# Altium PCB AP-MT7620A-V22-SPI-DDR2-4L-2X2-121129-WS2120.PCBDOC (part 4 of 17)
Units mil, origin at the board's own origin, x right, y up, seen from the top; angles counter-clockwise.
Board outline 7316 x 4279 mil, 4 copper layers (Top, Inner Layer 2, Inner Layer 3, Bottom), stack 35.4 mil thick; 640 components, 473 nets, 2041 pads, 2358 vias.
Unrouted connection lines stored in the file: 11.
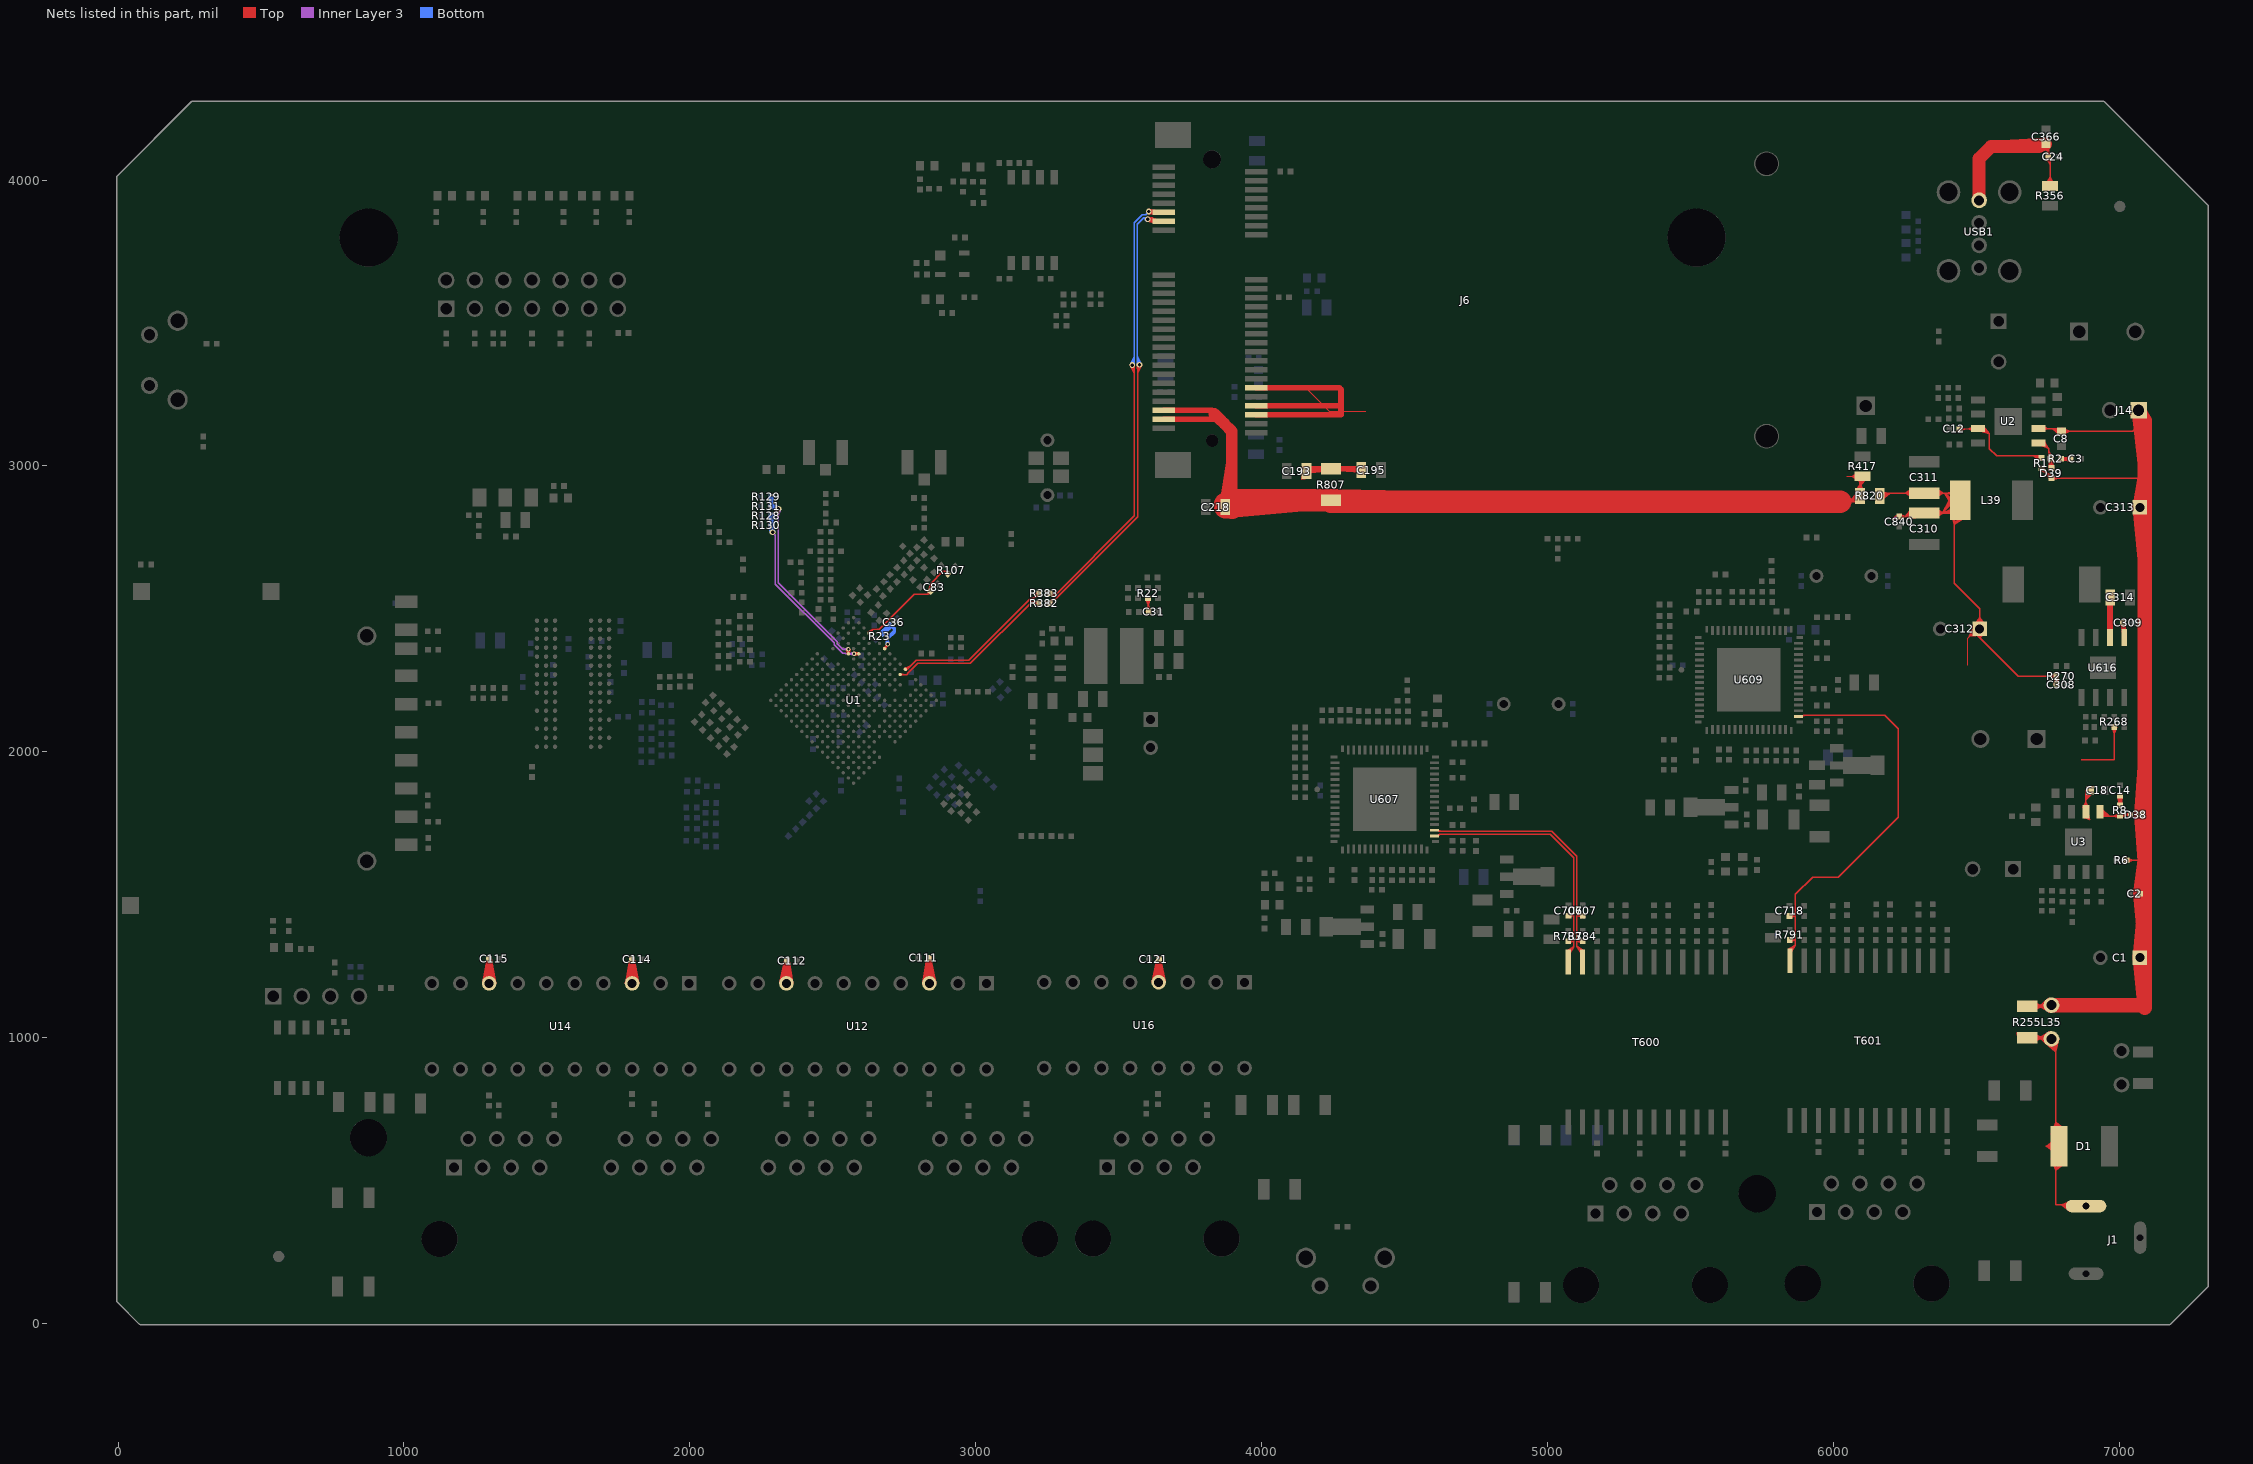
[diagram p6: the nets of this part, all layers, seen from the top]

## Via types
v1: diameter 20, hole 12, Top to Bottom, 2117 vias
v2: diameter 16, hole 8, Top to Bottom, 241 vias

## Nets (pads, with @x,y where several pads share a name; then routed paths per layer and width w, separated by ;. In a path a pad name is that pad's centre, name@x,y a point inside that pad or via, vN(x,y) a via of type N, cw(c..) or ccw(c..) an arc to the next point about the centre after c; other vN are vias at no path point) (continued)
5VA: C308.1 C310.1 C311.1 C312.1 C840.1 L39.2 R270.1 R820.2 | length 7481.4
  Top w4: 6206,2813.5 6219,2826.5 ; C840.1@6227.12,2829.99 6206.44,2813.94 ; C840.1@6229.33,2826.64 6206.44,2813.94 ; C840.1@6232.09,2819.15 6206.44,2813.94 ; C840.1@6232.59,2815.16 6206.44,2813.94 ; 6470.5,2302.5 6470.5,2398 6507.5,2435 C312.1@6511.9,2435 ; C312.1@6493.37,2444.6 6475.96,2403.46 ; C312.1@6497.09,2442.82 6475.96,2403.46 ; C312.1@6500.59,2440.73 6475.96,2403.46 ; C312.1@6503.86,2438.35 6475.96,2403.46 ; C312.1@6506.89,2435.7 6475.96,2403.46 ; C312.1@6515.87,2423.53 6475.96,2403.46 ; C312.1@6517.52,2419.86 6475.96,2403.46 ; C312.1@6518.83,2416.04 6475.96,2403.46 ; C312.1@6519.8,2412.07 6475.96,2403.46 ; C312.1@6520.41,2408 6475.96,2403.46 ; 6206.44,2813.94 C840.1@6231,2823 ; 6219,2826.5 6227.5,2826.5 C840.1@6231,2823 ; 6219,2826.5 6226.42,2816.44 6219,2826.5 ; 6219,2826.5 6230.66,2830.99 6219,2826.5 ; 6219,2826.5 6229.28,2819.39 6219,2826.5 ; 6219,2826.5 6231.49,2826.97 6219,2826.5 ; 6219,2826.5 C840.1@6231,2823 ; 6219,2826.5 C840.1@6231,2823
  Top w4.5: R820.2@6161.07,2905.16 6197.15,2904.88 ; R820.2@6161.32,2900.64 6197.15,2904.88 ; R820.2@6161.39,2909.71 6197.15,2904.88 ; R820.2@6164.46,2889.61 6197.15,2904.88 ; R820.2@6166.63,2885.64 6197.15,2904.88 ; R820.2@6169.3,2881.94 6197.15,2904.88 ; C840.1@6231,2823 6310,2823 6310,2827.12 C310.1@6318,2835.12 6438,2835.12 6438,2880 L39.2@6423,2880 ; C840.1@6231.22,2819.76 6254.5,2823 ; C840.1@6231.22,2826.24 6254.5,2823 ; C840.1@6232.28,2815.36 6254.5,2823 ; C840.1@6232.28,2830.64 6254.5,2823 ; C310.1@6274.76,2849.55 6251.11,2823 ; C310.1@6277.99,2846.27 6251.11,2823 ; C311.1@6279.96,2888.06 6251.35,2904.88 ; C311.1@6279.96,2921.7 6251.35,2904.88 ; C310.1@6280.74,2842.65 6251.11,2823 ; C311.1@6282.01,2892.19 6251.35,2904.88 ; C311.1@6282.01,2917.57 6251.35,2904.88 ; C310.1@6282.99,2838.74 6251.11,2823 ; C311.1@6283.46,2896.51 6251.35,2904.88 ; C311.1@6283.46,2913.25 6251.35,2904.88 ; C311.1@6284.3,2900.95 6251.35,2904.88 ; C311.1@6284.3,2908.81 6251.35,2904.88 ; C310.1@6284.54,2835.12 6251.11,2823 ; C311.1@6284.54,2904.88 6251.35,2904.88 ; C310.1@6285.67,2831.35 6251.11,2823 ; C310.1@6286.28,2817.77 6251.11,2823 ; C310.1@6286.45,2826.9 6251.11,2823 ; C310.1@6286.66,2822.36 6251.11,2823 ; C310.1@6351.46,2835.12 6384.65,2835.12 ; C311.1@6351.46,2904.88 6384.65,2904.88 ; C310.1@6351.7,2831.19 6384.65,2835.12 ; C310.1@6351.7,2839.05 6384.65,2835.12 ; C311.1@6351.7,2900.95 6384.65,2904.88 ; C311.1@6351.7,2908.81 6384.65,2904.88 ; C310.1@6352.54,2826.75 6384.65,2835.12 ; C310.1@6352.54,2843.49 6384.65,2835.12 ; C311.1@6352.54,2896.51 6384.65,2904.88 ; C311.1@6352.54,2913.25 6384.65,2904.88 ; C310.1@6353.99,2822.43 6384.65,2835.12 ; C310.1@6353.99,2847.81 6384.65,2835.12 ; C311.1@6353.99,2892.19 6384.65,2904.88 ; C311.1@6353.99,2917.57 6384.65,2904.88 ; C310.1@6356.04,2818.3 6384.65,2835.12 ; C310.1@6356.04,2851.94 6384.65,2835.12 ; C311.1@6356.04,2888.06 6384.65,2904.88 ; C311.1@6356.04,2921.7 6384.65,2904.88 ; L39.2@6409.66,2849.91 6423,2795.81 ; L39.2@6414.27,2850.84 6423,2795.81 ; L39.2@6418.38,2902.88 6380.26,2835.12 ; L39.2@6418.88,2851.37 6423,2795.81 ; L39.2@6421.33,2854.22 6389.1,2904.88 ; L39.2@6422.31,2900.51 6380.26,2835.12 ; L39.2@6423.47,2851.52 6423,2795.81 ; L39.2@6425.16,2856.87 6389.1,2904.88 ; L39.2@6426.09,2897.93 6380.26,2835.12 ; L39.2@6428.03,2851.3 6423,2795.81 ; L39.2@6428.75,2859.79 6389.1,2904.88 ; L39.2@6429.68,2895.14 6380.26,2835.12 ; L39.2@6432.07,2862.94 6389.1,2904.88 ; L39.2@6433.09,2892.16 6380.26,2835.12 ; L39.2@6435.13,2866.32 6389.1,2904.88 ; L39.2@6448.41,2895.48 6389.1,2904.88 ; L39.2@6448.47,2913.84 6389.1,2904.88 ; L39.2@6448.95,2900 6389.1,2904.88 ; L39.2@6448.99,2909.2 6389.1,2904.88 ; L39.2@6449.15,2904.58 6389.1,2904.88 ; L39.2@6451.66,2865.9 6380.26,2835.12 ; L39.2@6453.33,2861.69 6380.26,2835.12 ; L39.2@6454.76,2857.37 6380.26,2835.12 ; L39.2@6455.94,2852.95 6380.26,2835.12 ; L39.2@6456.86,2848.45 6380.26,2835.12 ; L39.2@6457.72,2839.39 6423,2795.81 ; L39.2@6461.17,2836.4 6423,2795.81 ; L39.2@6464.39,2833.11 6423,2795.81 ; L39.2@6467.35,2829.54 6423,2795.81 ; L39.2@6470.03,2825.69 6423,2795.81 ; C312.1@6489.62,2436.97 6511.9,2469.09 ; C312.1@6490.35,2421.04 6511.9,2399.6 ; C312.1@6493.61,2434.54 6511.9,2469.09 ; C312.1@6493.98,2424.16 6511.9,2399.6 ; C312.1@6497.8,2432.63 6511.9,2469.09 ; C312.1@6497.96,2426.62 6511.9,2399.6 ; C312.1@6502.13,2431.24 6511.9,2469.09 ; C312.1@6502.19,2428.41 6511.9,2399.6 ; C312.1@6506.57,2430.36 6511.9,2469.09 ; C312.1@6506.58,2429.53 6511.9,2399.6 ; C312.1@6511.9,2430 C312.1@6511.9,2435 ; C312.1@6517.22,2429.53 6511.9,2399.6 ; C312.1@6517.23,2430.36 6511.9,2469.09 ; C312.1@6521.61,2428.41 6511.9,2399.6 ; C312.1@6521.66,2431.24 6511.9,2469.09 ; C312.1@6525.83,2426.62 6511.9,2399.6 ; C312.1@6526,2432.63 6511.9,2469.09 ; C312.1@6529.81,2424.16 6511.9,2399.6 ; C312.1@6530.18,2434.54 6511.9,2469.09 ; C312.1@6533.45,2421.04 6511.9,2399.6 ; C312.1@6534.17,2436.97 6511.9,2469.09 ; C308.1@6772.27,2235.5 R270.1@6777.63,2258.5 ; C308.1@6772.28,2234.36 R270.1@6774.18,2258.42 ; R270.1@6772.36,2263.72 C308.1@6780,2241.5 ; C308.1@6772.52,2237.03 R270.1@6782.37,2258.5 ; C308.1@6772.88,2238.05 R270.1@6785.82,2258.42 ; C308.1@6776.75,2234.9 R270.1@6777.63,2258.5 ; R270.1@6776.76,2264.78 C308.1@6780,2241.5 ; C308.1@6776.8,2234.43 R270.1@6774.18,2258.42 ; C308.1@6776.8,2235.55 R270.1@6782.37,2258.5 ; C308.1@6776.91,2235.99 R270.1@6785.82,2258.42 ; R270.1@6778.72,2257.36 6756.5,2265 ; R270.1@6778.72,2272.64 6756.5,2265 ; R270.1@6779.78,2261.76 6756.5,2265 ; R270.1@6779.78,2268.24 6756.5,2265 ; C308.1@6783.09,2235.99 R270.1@6774.18,2258.42 ; C308.1@6783.2,2234.43 R270.1@6785.82,2258.42 ; C308.1@6783.2,2235.55 R270.1@6777.63,2258.5 ; C308.1@6783.25,2234.9 R270.1@6782.37,2258.5 ; R270.1@6783.24,2264.78 C308.1@6780,2241.5 ; C308.1@6787.12,2238.05 R270.1@6774.18,2258.42 ; C308.1@6787.48,2237.03 R270.1@6777.63,2258.5 ; R270.1@6787.64,2263.72 C308.1@6780,2241.5 ; C308.1@6787.72,2234.36 R270.1@6785.82,2258.42 ; C308.1@6787.73,2235.5 R270.1@6782.37,2258.5 ; 6197.15,2904.88 R820.2@6162.45,2895 6172.33,2904.88 C311.1@6318,2904.88 6438,2904.88 6443.75,2899.13 L39.2@6443.75,2880 L39.2@6423,2880 ; L39.2@6423,2880 6423,2590 6511.9,2501.1 C312.1@6511.9,2435 ; 6511.9,2399.6 6646.5,2265 R270.1@6780,2265 ; 6511.9,2399.6 C312.1@6511.9,2435 ; 6756.5,2265 R270.1@6780,2265 ; R270.1@6774.18,2258.42 C308.1@6780,2235 ; R270.1@6777.63,2258.5 C308.1@6780,2235 ; C308.1@6780,2235 R270.1@6780,2265 ; C308.1@6780,2235 R270.1@6780,2258.5 ; C308.1@6780,2235 R270.1@6785.82,2258.42 ; C308.1@6780,2235 R270.1@6782.37,2258.5 ; C308.1@6780,2241.5 R270.1@6780,2265 ; R270.1@6780,2258.5 6772.36,2236.28 R270.1@6780,2258.5 ; R270.1@6780,2258.5 6787.64,2236.28 R270.1@6780,2258.5 ; R270.1@6780,2258.5 6776.76,2235.22 R270.1@6780,2258.5 ; R270.1@6780,2258.5 6783.24,2235.22 R270.1@6780,2258.5
5VD_0: C24.1 C366.1 R356.2 USB1.1 | length 1538.3
  Top w4: R356.2@6758,3979.45 6758.5,3979.45 R356.2@6770.45,3967.5
  Top w4.5: C366.1@6735.01,4135.86 6719.8,4117.3 ; C366.1@6735.15,4121.89 6752,4096.75 ; C366.1@6738.27,4132.62 6719.8,4117.3 ; C366.1@6739.12,4124.13 6752,4096.75 ; C366.1@6740.81,4128.89 6719.8,4117.3 ; C366.1@6742,4126.41 6719.8,4117.3 ; C366.1@6742.9,4123.81 6719.8,4117.3 ; C366.1@6743.33,4125.74 6752,4096.75 ; C366.1@6743.66,4114.78 6719.8,4117.3 ; R356.2@6743.69,3983.02 6758,4009.95 ; C366.1@6743.71,4119.36 6719.8,4117.3 ; C24.1@6744.36,4082.28 6752,4104.5 ; C24.1@6744.77,4078.2 6758,4054.77 ; C366.1@6746,4126.41 6752,4096.75 ; R356.2@6747.9,3981.17 6758,4009.95 ; C366.1@6748.72,4126.83 6752,4096.75 ; C24.1@6748.76,4081.22 6752,4104.5 ; C24.1@6748.88,4080.09 6758,4054.77 ; R356.2@6752.28,3979.99 6758,4009.95 ; C366.1@6753.23,4126.99 6752,4096.75 ; C24.1@6755.21,4081.53 6758,4054.77 ; C24.1@6755.24,4081.22 6752,4104.5 ; C366.1@6757.75,4126.46 6752,4096.75 ; R356.2@6758,3979.45 6758,4075 C24.1@6752,4081 ; C24.1@6759.64,4082.28 6752,4104.5 ; C24.1@6759.73,4081.62 6758,4054.77 ; R356.2@6763.72,3979.99 6758,4009.95 ; R356.2@6768.1,3981.17 6758,4009.95 ; R356.2@6772.31,3983.02 6758,4009.95 ; 6719.8,4117.3 6728.91,4126.41 C366.1@6744,4126.41 6752,4118.41 C24.1@6752,4081 ; C24.1@6752,4081 6758,4054.77
  Top w45: USB1.1@6510,3929 6510,4075.3 6552,4117.3 6719.8,4117.3 6742,4126.41 6590.95,4117.3
5VD_E: C218.1 J6.47 J6.49 R417.1 R807.1 R820.1 | length 5514.4
  Top w4: 6047.5,2964.05 R417.1@6102.5,2964.05 ; R417.1@6087.62,2949.56 6062.5,2964.05 ; R417.1@6087.62,2978.54 6062.5,2964.05 ; R417.1@6089.41,2953.25 6062.5,2964.05 ; R417.1@6089.41,2974.85 6062.5,2964.05 ; R417.1@6090.66,2957.1 6062.5,2964.05 ; R417.1@6090.66,2971 6062.5,2964.05 ; R417.1@6091.34,2961.06 6062.5,2964.05 ; R417.1@6091.34,2967.05 6062.5,2964.05 ; R417.1@6091.5,2964.05 6062.5,2964.05
  Top w4.5: 3852,3163.11 3852.44,3163.56 3853.44,3163.56 ; C218.1@3873.45,2856 3894.7,2856 ; C218.1@3874.23,2850.3 3894.7,2856 ; C218.1@3874.23,2861.7 3894.7,2856 ; C218.1@3875.92,2846.05 3894.7,2856 ; C218.1@3875.92,2865.95 3894.7,2856 ; C218.1@3878.57,2842.17 3894.7,2856 ; C218.1@3878.57,2869.83 3894.7,2856 ; 3896,2854.7 3894.7,2856 ; 6018,2869.45 6023.55,2875 ; 6023,2875 6023.55,2875 ; R820.1@6079.24,2909.57 6093.55,2936.5 ; R820.1@6083.45,2907.72 6093.55,2936.5 ; R820.1@6084.24,2906.44 6057.29,2875 ; R820.1@6087.53,2903.29 6057.29,2875 ; R417.1@6087.77,2964.75 6093.55,2931.1 ; R820.1@6087.83,2906.54 6093.55,2936.5 ; R820.1@6090.43,2899.83 6057.29,2875 ; R417.1@6092.32,2965.22 6093.55,2931.1 ; R820.1@6093.55,2906 6093.55,2936.5 ; R820.1@6095.97,2889.78 6057.29,2875 ; R417.1@6096.84,2965.09 6093.55,2931.1 ; R820.1@6097.35,2885.48 6057.29,2875 ; R820.1@6098.26,2881.02 6057.29,2875 ; R820.1@6099.28,2906.54 6093.55,2936.5 ; R820.1@6103.66,2907.72 6093.55,2936.5 ; R820.1@6107.86,2909.57 6093.55,2936.5 ; R417.1@6107.9,2962.08 6093.55,2931.1 ; R417.1@6111.88,2959.91 6093.55,2931.1 ; R417.1@6115.56,2957.2 6093.55,2931.1 ; 6023.55,2875 6093.55,2875 R820.1@6093.55,2895 ; 6057.29,2875 R820.1@6093.55,2895 ; R820.1@6093.55,2895 6093.55,2955.1 R417.1@6102.5,2964.05 6093.55,2931.1
  Top w20: J6.49@3658,3163.11 3852,3163.11 ; J6.47@3658,3194.61 3826,3194.61 3845,3175.61 3845,3172 ; J6.49@3687.53,3163.11 3757.37,3163.11 ; J6.47@3687.53,3194.61 3757.37,3194.61
  Top w40: 3834.5,3183 3868.75,3148.75 3868.75,3148.25 ; 3845,3172 3853.44,3163.56 3868.75,3148.25 ; 3896,3010.51 C218.1@3873.45,2867 ; 3868.75,3148.25 3896,3121 3896,2879.88 ; C218.1@3873.45,2867 3896,2879.88 ; C218.1@3873.45,2867 3896,2872 3896,2879.88 ; C218.1@3873.45,2867 3896,2879.88
  Top w80: 3967.57,2879.88 R807.1@4227.25,2879.88 ; 4141.88,2879.88 C218.1@3873.45,2856 3896,2854.7 3896,2872 3873.45,2867 3896,2879.88 R807.1@4243,2879.88 4243,2875 6023,2875 ; R807.1@4258.75,2879.88 4518.75,2875
5VD_E_A: C193.1 C195.1 J6.42 J6.46 J6.48 R807.2 | length 2497.6
  Top w4: J6.42@3980.83,3273.35 4034.73,3273.35 4035.58,3272.5 ; J6.42@4010.36,3273.35 4032.2,3273.35 ; J6.42@4010.7,3269.52 4032.2,3273.35 ; J6.42@4010.7,3277.17 4032.2,3273.35 ; J6.42@4011.77,3265.63 4032.2,3273.35 ; J6.42@4011.77,3281.06 4032.2,3273.35 ; C193.1@4143.98,2977.61 4140.5,2953.5 ; C193.1@4148.02,2976.67 4140.5,2953.5 ; C193.1@4151.77,2975.1 4140.5,2953.5 ; C193.1@4155.17,2972.95 4140.5,2953.5 ; 4155.5,3272.5 4236,3192 4364.5,3192 ; C193.1@4157.45,2971 4140.5,2953.5 ; C193.1@4157.45,2982 4157.5,2981.95 4157.5,2970.5 4140.5,2953.5 ; C193.1@4159.47,2968.78 4140.5,2953.5 ; C193.1@4161.73,2965.46 4140.5,2953.5 ; C193.1@4163.42,2961.76 4140.5,2953.5 ; C193.1@4164.49,2957.75 4140.5,2953.5
  Top w20: J6.48@3980.83,3178.86 4278,3178.86 4278,3210.35 ; J6.46@3980.83,3210.35 4278,3210.35 ; J6.42@3980.83,3273.35 4272.15,3273.35 4278,3267.5 4278,3210.35 ; J6.48@4010.36,3178.86 4080.2,3178.86 ; J6.46@4010.36,3210.35 4080.2,3210.35 ; J6.42@4010.36,3273.35 4080.2,3273.35 ; R807.2@4236.58,2990.12 C193.1@4157.45,2982 ; R807.2@4258.75,2990.12 C195.1@4338.43,2990.12 ; R807.2@4270.4,2990.12 C195.1@4348.55,2985 ; R807.2@4270.8,2990.12 C195.1@4348.55,2985 ; C193.1@4157.45,2982 C193.1@4165.57,2990.12 ; C193.1@4157.45,2982 4227.25,2990.12 C193.1@4165.57,2990.12 ; C193.1@4165.57,2990.12 R807.2@4243,2990.12 4343.43,2990.12 C195.1@4348.55,2985
5VEN_5-POWER0: C12.1 R1.2 U2.7 | length 949.2
  Top w4: C12.1@6440.75,3130.25 6441.5,3131 U2.7@6506.39,3131 U2.7@6528,3131 ; C12.1@6441,3130 6463.04,3131 ; C12.1@6441.18,3134 6463.04,3131 ; C12.1@6441.54,3126.04 6463.04,3131 ; C12.1@6442.09,3137.93 6463.04,3131 ; C12.1@6442.81,3122.21 6463.04,3131 ; U2.7@6492.13,3121.02 6470.08,3131 ; U2.7@6492.13,3140.98 6470.08,3131 ; U2.7@6493.49,3124.85 6470.08,3131 ; U2.7@6493.49,3137.15 6470.08,3131 ; U2.7@6494.18,3128.8 6470.08,3131 ; U2.7@6494.18,3133.2 6470.08,3131 ; U2.7@6494.28,3131 6470.08,3131 ; R1.2@6719.91,3035 6721,3035 R1.2@6728,3028
  Top w4.5: C12.1@6440.75,3130.25 C12.1@6441,3130 ; U2.7@6514.43,3121.91 6545.59,3113.41 ; U2.7@6515.92,3126.19 6545.59,3113.41 ; U2.7@6518.5,3131 6545.59,3113.41 ; U2.7@6521.84,3135.31 6545.59,3113.41 ; U2.7@6525.14,3138.41 6545.59,3113.41 ; U2.7@6528,3131 6546,3113 6546,3060 6571,3035 R1.2@6719.91,3035 ; R1.2@6725.17,3020.79 6699.59,3035 ; R1.2@6727.05,3024.89 6699.59,3035 ; R1.2@6728,3028 6699.59,3035 ; R1.2@6728.6,3031.19 6699.59,3035 ; R1.2@6728.84,3035.7 6699.59,3035
12V: C1.1 C2.1 C8.1 C18.1 C313.1 C314.1 D38.1 D39.1 J14.1 L35.2 R1.1 R6.1 R255.2 R268.1 U2.2 U3.2 U616.2 | length 9168.6
  Top w4: C8.1@6795.89,3131 6798,3128.89 C8.1@6798,3120.59 ; U3.2@6877.16,1770.14 6897,1762.5 ; U3.2@6878.98,1773.78 6897,1762.5 ; U3.2@6881.42,1776.97 6897,1762.5 ; U3.2@6883,1778.5 6897,1762.5 ; U3.2@6883,1790.61 6884,1789.61 6884,1775.5 6897,1762.5 ; U3.2@6884.73,1779.87 6897,1762.5 ; U3.2@6888.22,1781.86 6897,1762.5 ; U3.2@6892.07,1783.18 6897,1762.5
  Top w4.5: R255.2@6678,1110.12 6759.06,1110.12 L35.2@6763,1114.06 ; R255.2@6693.75,1110.12 6726.93,1110.12 ; R255.2@6693.98,1106.19 6726.93,1110.12 ; R255.2@6693.98,1114.05 6726.93,1110.12 ; R255.2@6694.82,1101.75 6726.93,1110.12 ; R255.2@6694.82,1118.49 6726.93,1110.12 ; R255.2@6696.27,1097.43 6726.93,1110.12 ; R255.2@6696.27,1122.81 6726.93,1110.12 ; R255.2@6698.33,1093.3 6726.93,1110.12 ; R255.2@6698.33,1126.94 6726.93,1110.12 ; U2.2@6717.61,3131 6748,3131 ; R1.1@6723.51,2985.68 6747.88,2973.12 ; U2.2@6724.5,3131 6748,3131 ; R1.1@6725.91,2989.51 6747.88,2973.12 ; R1.1@6730.37,2994.22 6747.88,2973.12 ; R1.1@6734.08,2996.81 6747.88,2973.12 ; L35.2@6753.03,1137.25 6721.85,1110.12 ; L35.2@6755.9,1133.55 6721.85,1110.12 ; D39.1@6756.68,2952.51 6744.08,2976.92 ; L35.2@6757.61,1089.39 6721.85,1110.12 ; L35.2@6758.3,1129.61 6721.85,1110.12 ; L35.2@6759.73,1093.56 6721.85,1110.12 ; L35.2@6760.23,1125.47 6721.85,1110.12 ; D39.1@6760.52,2954.9 6744.08,2976.92 ; L35.2@6761.34,1097.89 6721.85,1110.12 ; L35.2@6761.68,1121.18 6721.85,1110.12 ; L35.2@6762.45,1102.32 6721.85,1110.12 ; L35.2@6763.05,1106.8 6721.85,1110.12 ; D39.1@6763.22,2953.76 6786.5,2957 ; D39.1@6763.22,2960.24 6786.5,2957 ; D39.1@6764.28,2949.36 6786.5,2957 ; D39.1@6764.28,2964.64 6786.5,2957 ; D39.1@6765.22,2959.37 6744.08,2976.92 ; D39.1@6767.81,2963.08 6744.08,2976.92 ; C8.1@6790.03,3110.47 6766.8,3131 ; C8.1@6792.78,3114.09 6766.8,3131 ; C8.1@6794.96,3118.04 6766.8,3131 ; C8.1@6795.89,3131 6748,3131 ; C8.1@6796,3120.59 6766.8,3131 ; C8.1@6796.81,3123.22 6766.8,3131 ; C8.1@6797.62,3127.66 6766.8,3131 ; C8.1@6797.78,3132.21 6766.8,3131 ; C8.1@6798,3120.59 7048,3120.59 7072.91,3145.5 7089,3145.5 ; C8.1@6800,3120.59 6827.5,3120.59 ; C8.1@6800.14,3117.84 6827.5,3120.59 ; C8.1@6800.14,3123.34 6827.5,3120.59 ; C8.1@6800.96,3113.4 6827.5,3120.59 ; C8.1@6800.96,3127.78 6827.5,3120.59 ; C8.1@6802.51,3109.11 6827.5,3120.59 ; C8.1@6802.51,3132.07 6827.5,3120.59 ; 6866.5,1971.5 6983,1971.5 R268.1@6983,2087 ; U3.2@6883,1790.61 6883,1824.5 ; U3.2@6883,1797.5 6883,1824.5 ; C18.1@6886.09,1866.16 6883,1833.28 ; C18.1@6890.58,1865.43 6883,1833.28 ; C18.1@6894.89,1864.1 6883,1833.28 ; C18.1@6899.83,1861.7 6883,1833.28 ; C18.1@6902,1863.41 6883,1863.41 ; C18.1@6903.55,1859.14 6883,1833.28 ; C18.1@6906.9,1856.07 6883,1833.28 ; R268.1@6975.36,2085.72 6983,2063.5 ; R268.1@6979.76,2086.78 6983,2063.5 ; R268.1@6983,2088 R268.1@6983,2087 ; R268.1@6986.24,2086.78 6983,2063.5 ; R268.1@6990.64,2085.72 6983,2063.5 ; R6.1@7026,1621 7088,1621 7089,1620 ; R6.1@7026.22,1617.76 7049.5,1621 ; R6.1@7026.22,1624.24 7049.5,1621 ; R6.1@7027.28,1613.36 7049.5,1621 ; R6.1@7027.28,1628.64 7049.5,1621 ; D38.1@7071.25,1786.12 7089,1795 ; C313.1@7071.9,2855 C313.1@7089,2855 ; C2.1@7073,1504 7088,1504 ; C2.1@7073.35,1500.77 7088,1504 ; C2.1@7073.35,1507.23 7088,1504 ; D38.1@7073.73,1782.32 7089,1795 ; C2.1@7075,1496.51 7088,1504 ; C2.1@7075,1511.49 7088,1504 ; D38.1@7076.41,1776.78 7089,1780 ; D38.1@7076.41,1783.22 7089,1780 ; D38.1@7078.31,1772.6 7089,1780 ; D38.1@7078.31,1787.4 7089,1780 ; D38.1@7078.62,1778.08 7089,1795 ; D38.1@7082.73,1776.17 7089,1795 ; 7089,1505 7088,1504 ; 7089,2957 D39.1@6763,2957 ; 6744.08,2976.92 D39.1@6763,2957 ; 6747.88,2973.12 R1.1@6728,2992 6728,2993 6758,2963 6758,2962 D39.1@6763,2957 ; 6748,3131 6732.43,3140.58 6748,3131 ; 6748,3131 6732.43,3121.42 6748,3131 ; 6748,3131 6730.53,3136.39 6748,3131 ; 6748,3131 6730.53,3125.61 6748,3131 ; 6748,3131 6729.72,3131 6748,3131 ; 6883,1824.5 6883,1863.41 ; 6883,1824.5 6873.31,1804.99 6883,1824.5 ; 6883,1824.5 6892.69,1804.99 6883,1824.5 ; 6883,1824.5 6877.59,1803.4 6883,1824.5 ; 6883,1824.5 6888.41,1803.4 6883,1824.5 ; 6883,1824.5 6883,1802.72 6883,1824.5 ; 6883,1833.28 C18.1@6897.41,1863 ; 6883,1863.41 6892.32,1852.41 6883,1863.41 ; 6883,1863.41 6892.93,1873.86 6883,1863.41 ; 6883,1863.41 6895.39,1856.04 6883,1863.41 ; 6883,1863.41 6895.79,1870.07 6883,1863.41 ; 6883,1863.41 6897.07,1860.27 6883,1863.41 ; 6883,1863.41 6897.22,1865.74 6883,1863.41 ; 6883,1863.41 C18.1@6897.41,1863 ; 6883,1863.41 C18.1@6897.41,1863 ; 6983,2063.5 R268.1@6983,2087 ; D38.1@7076,1780 7089,1780 ; D38.1@7076,1780 7076,1782 7089,1795 ; D38.1@7076,1780 7089,1795
  Top w20: U616.2@6968,2399.33 6968,2539.45 C314.1@6968.55,2540 ; U616.2@6968,2418.82 6968,2488.86 ; 6968,2452 C314.1@6968.55,2529
  Top w50: L35.2@6763,1114.06 7079.94,1114.06 7089,1105 ; 7089,1335.47 C2.1@7073,1504 ; 7089,1459.74 C1.1@7071.9,1280 7089,1105 ; 7089,1946.31 D38.1@7076,1780 ; 7089,2674.45 C313.1@7071.9,2855 7089,2957 ; J14.1@7068,3195 7063,3190 7063,3185.05 7089,3159.05 ; J14.1@7068,3195 7089,3159.05 ; J14.1@7068,3195 7089,3159.05 ; J14.1@7068,3195 7089,3145.5 ; J14.1@7068,3195 7089,3159.05 ; J14.1@7068,3195 7089,3010.63 J14.1@7068,3195 ; J14.1@7068,3195 7089,3145.5 ; C2.1@7073,1504 7089,1620 ; C2.1@7073,1504 7089,1505 ; C2.1@7073,1504 7089,1505 ; D38.1@7076,1780 7089,1780 ; D38.1@7076,1780 7089,1620 ; D38.1@7076,1780 7089,1795 ; D38.1@7076,1780 7089,1780 ; D38.1@7076,1780 7089,1795 ; 7089,1105 7089,1505 ; 7089,1505 7089,1620 ; 7089,1620 7089,1780 ; 7089,1780 7089,1795 ; 7089,1795 7089,2855 7089,2957 ; 7089,2957 7089,3159.05 ; 7089,2957 7089,3145.5 ; 7089,3145.5 7089,3159.05
12V_L_5-POWER0: D1.2 J1.3 L35.1 R255.1 | length 4520.9
  Top w4: R255.1@6647.35,990.36 6640.5,1017.5 ; R255.1@6651.3,991.68 6640.5,1017.5 ; R255.1@6654.95,993.52 6640.5,1017.5 ; R255.1@6658.24,995.85 6640.5,1017.5 ; R255.1@6662.25,999.88 6640.5,1017.5 ; R255.1@6665.36,1004.64 6640.5,1017.5 ; R255.1@6666.95,1008.35 6640.5,1017.5 ; R255.1@6668,1012.3 6640.5,1017.5 ; R255.1@6668.47,1016.44 6640.5,1017.5 ; R255.1@6678,999.88 6663.88,999.88 6661,997 6640.5,1017.5
  Top w4.5: R255.1@6678,999.88 L35.1@6768.12,999.88 ; R255.1@6693.75,999.88 6726.93,999.88 ; R255.1@6693.98,995.95 6726.93,999.88 ; R255.1@6693.98,1003.81 6726.93,999.88 ; R255.1@6694.82,991.51 6726.93,999.88 ; R255.1@6694.82,1008.25 6726.93,999.88 ; R255.1@6696.27,987.19 6726.93,999.88 ; R255.1@6696.27,1012.57 6726.93,999.88 ; R255.1@6698.33,983.06 6726.93,999.88 ; R255.1@6698.33,1016.7 6726.93,999.88 ; L35.1@6742,981.92 6778,950.74 ; 6742.17,620 6778,620 6778,535 ; L35.1@6745.2,985.28 6778,950.74 ; L35.1@6748.68,988.27 6778,950.74 ; L35.1@6752.39,990.9 6778,950.74 ; L35.1@6753.02,972.75 6721.89,999.88 ; L35.1@6755.9,976.45 6721.89,999.88 ; L35.1@6756.31,993.14 6778,950.74 ; L35.1@6757.61,1020.61 6721.89,999.88 ; L35.1@6758.3,980.39 6721.89,999.88 ; L35.1@6759.73,1016.44 6721.89,999.88 ; L35.1@6760.23,984.53 6721.89,999.88 ; L35.1@6761.34,1012.11 6721.89,999.88 ; L35.1@6761.68,988.82 6721.89,999.88 ; D1.2@6762.18,662.74 6778,704.96 ; L35.1@6762.44,1007.68 6721.89,999.88 ; L35.1@6763,995.94 6772.06,995.94 6776.7,991.3 L35.1@6768.12,999.88 ; L35.1@6763.06,1003.2 6721.89,999.88 ; D1.2@6766.64,661.32 6778,704.96 ; L35.1@6770.04,997.7 6778,950.74 ; D1.2@6771.16,660.39 6778,704.96 ; L35.1@6774.52,998.24 6778,950.74 ; D1.2@6775.71,659.93 6778,704.96 ; L35.1@6779.07,998.36 6778,950.74 ; D1.2@6780.25,659.93 6778,704.96 ; D1.2@6780.77,594.13 6746.39,620 ; D1.2@6780.77,645.87 6746.39,620 ; D1.2@6783.39,598.03 6746.39,620 ; D1.2@6783.39,641.97 6746.39,620 ; L35.1@6783.65,998.03 6778,950.74 ; D1.2@6785.54,602.14 6746.39,620 ; D1.2@6785.54,637.86 6746.39,620 ; D1.2@6787.21,606.4 6746.39,620 ; D1.2@6787.21,633.6 6746.39,620 ; L35.1@6788.22,997.26 6778,950.74 ; D1.2@6788.42,610.78 6746.39,620 ; D1.2@6788.42,629.22 6746.39,620 ; D1.2@6798.1,664.6 6778,704.96 ; D1.2@6802.06,666.82 6778,704.96 ; D1.2@6805.8,669.45 6778,704.96 ; D1.2@6809.28,672.48 6778,704.96 ; D1.2@6812.48,675.9 6778,704.96 ; J1.3@6827.39,393.06 6799.62,415 ; J1.3@6830.02,396.88 6799.62,415 ; J1.3@6831.61,430.14 6799.62,415 ; J1.3@6832.1,400.95 6799.62,415 ; J1.3@6833.32,425.83 6799.62,415 ; J1.3@6833.63,405.21 6799.62,415 ; J1.3@6834.43,421.4 6799.62,415 ; J1.3@6834.79,411 6799.62,415 ; J1.3@6834.96,416.9 6799.62,415 ; J1.3@6884,411 6888,415 6778,415 6778,535 ; L35.1@6768.12,999.88 6778,990 6778,535 ; 6778,535.61 6812.38,563.93 6778,535.61 ; 6778,535.61 6762.18,577.24 6778,535.61 ; 6778,535.61 6809.21,567.39 6778,535.61 ; 6778,535.61 6766.64,578.68 6778,535.61 ; 6778,535.61 6805.75,570.45 6778,535.61 ; 6778,535.61 6771.16,579.62 6778,535.61 ; 6778,535.61 6802.03,573.11 6778,535.61 ; 6778,535.61 6775.71,580.09 6778,535.61 ; 6778,535.61 6798.09,575.36 6778,535.61 ; 6778,535.61 6780.25,580.09 6778,535.61
AA_1-CPU-RT0: C31.2 R22.1 | length 284
  Top w4.5: R22.1@3595.36,2535.72 3603,2513.5 ; C31.2@3597.27,2490.62 3603,2513.65 ; R22.1@3599.76,2536.78 3603,2513.5 ; C31.2@3601.75,2489.95 3603,2513.65 ; R22.1@3606.24,2536.78 3603,2513.5 ; C31.2@3608.21,2490.49 3603,2513.65 ; R22.1@3610.64,2535.72 3603,2513.5 ; C31.2@3612.51,2491.9 3603,2513.65 ; 3603,2513.5 R22.1@3603,2537 3603,2492 C31.2@3605,2490 3603,2513.65
ANT_TRN: R128.2 R130.2 U1.D5 | length 2646.2
  Top w4.5: v2@2574.41,2348.54 U1.D5@2590.69,2346.49 ; v2@2574.45,2337.06 U1.D5@2590.69,2339.22 ; v2@2576.92,2348.1 U1.D5@2590.69,2339.22 ; v2@2576.95,2337.51 U1.D5@2590.69,2346.49 ; v2(2574.7,2342.8) v2@2574.76,2342.86 ; v2(2574.7,2342.8) U1.D5@2591.1,2342.86 ; v2(2574.7,2342.8) U1.D5@2590.69,2339.22 ; v2(2574.7,2342.8) U1.D5@2590.69,2346.49 ; v2(2574.7,2342.8) U1.D5@2591.1,2342.86 ; v2@2574.76,2342.86 U1.D5@2591.1,2342.86 ; v2@2574.76,2342.86 U1.D5@2590.69,2339.22 ; v2@2574.76,2342.86 U1.D5@2590.69,2346.49 ; v2@2574.76,2342.86 U1.D5@2591.1,2342.86 ; U1.D5@2591.1,2342.86 2575.69,2348.46 U1.D5@2591.1,2342.86 ; U1.D5@2591.1,2342.86 2575.73,2337.14 U1.D5@2591.1,2342.86
  Inner Layer 3 w4.5: v1(2289.5,2768.5) 2299.64,2758.36 2299.64,2587 2504.64,2382 2504.64,2375.36 2535.5,2344.5 2544.4,2344.5 2546.1,2342.8 v2(2574.7,2342.8) ; v2@2574,2337.09 2551.2,2342.8 v2@2574,2348.51
  Bottom w4.5: R128.2@2278.27,2825.98 2283.71,2803.05 ; R128.2@2278.26,2826.93 R130.2@2280.78,2802.27 ; R130.2@2278.31,2793.95 R128.2@2285,2816.52 ; R128.2@2278.31,2825.55 R130.2@2285,2802.98 ; R128.2@2278.33,2825.39 R130.2@2285.62,2802.04 ; R128.2@2278.44,2824.77 R130.2@2287.78,2801.3 ; R128.2@2278.71,2823.87 R130.2@2291.15,2800.81 ; v1@2281.75,2768.3 R130.2@2285,2793 ; v1@2281.75,2768.62 R130.2@2286,2793 ; v1@2281.8,2767.6 R130.2@2282.75,2792.91 ; v1@2281.84,2769.66 R130.2@2289.23,2792.61 ; v1@2282.08,2766.25 R130.2@2278.32,2791.98 ; v1@2282.21,2771.12 R130.2@2293.56,2791.29 ; R130.2@2282.75,2793.09 R128.2@2285,2816.52 ; R128.2@2282.75,2826.34 R130.2@2285.62,2802.04 ; R128.2@2282.75,2826.41 R130.2@2285,2802.98 ; R128.2@2282.75,2826.59 2283.71,2803.05 ; R128.2@2282.78,2826.06 R130.2@2287.78,2801.3 ; R128.2@2282.78,2826.98 R130.2@2280.78,2802.27 ; R128.2@2282.86,2825.66 R130.2@2291.15,2800.81 ; v1@2286.27,2768.12 R130.2@2285,2793 ; v1@2286.26,2768.25 R130.2@2286,2793 ; v1@2286.25,2768.68 R130.2@2289.23,2792.61 ; v1@2286.32,2767.84 R130.2@2282.75,2792.91 ; v1@2286.35,2769.29 R130.2@2293.56,2791.29 ; v1@2286.48,2767.29 R130.2@2278.32,2791.98 ; R128.2@2289.13,2825.61 R130.2@2280.78,2802.27 ; R128.2@2289.21,2825.96 2283.71,2803.05 ; R128.2@2289.22,2826.94 R130.2@2291.15,2800.81 ; R130.2@2289.23,2793.36 R128.2@2285,2816.52 ; R128.2@2289.23,2826.14 R130.2@2285,2802.98 ; R128.2@2289.24,2826.23 R130.2@2285.62,2802.04 ; R128.2@2289.25,2826.52 R130.2@2287.78,2801.3 ; v1@2292.34,2770.08 R130.2@2278.32,2791.98 ; v1@2292.57,2769.57 R130.2@2282.75,2792.91 ; v1@2292.65,2769.29 R130.2@2285,2793 ; v1@2292.68,2769.17 R130.2@2286,2793 ; v1@2292.73,2768.16 R130.2@2293.56,2791.29 ; v1@2292.74,2768.76 R130.2@2289.23,2792.61 ; R128.2@2293.23,2823.7 R130.2@2280.78,2802.27 ; R128.2@2293.48,2824.49 2283.71,2803.05 ; R130.2@2293.58,2794.6 R128.2@2285,2816.52 ; R128.2@2293.58,2824.9 R130.2@2285,2802.98 ; R128.2@2293.63,2825.15 R130.2@2285.62,2802.04 ; R128.2@2293.72,2825.85 R130.2@2287.78,2801.3 ; R128.2@2293.74,2826.88 R130.2@2291.15,2800.81 ; v1@2295.92,2772.84 R130.2@2278.32,2791.98 ; v1@2296.57,2771.68 R130.2@2282.75,2792.91 ; v1@2296.81,2771.07 R130.2@2285,2793 ; v1@2296.91,2770.78 R130.2@2286,2793 ; v1@2297.13,2769.83 R130.2@2289.23,2792.61 ; v1@2297.25,2768.44 R130.2@2293.56,2791.29 ; R130.2@2278.32,2791.98 v1@2285,2771 ; R130.2@2278.32,2791.98 v1(2289.5,2768.5) ; R130.2@2280.78,2802.27 R128.2@2286,2826.5 ; R130.2@2282.75,2792.91 v1@2285,2771 ; R130.2@2282.75,2792.91 v1(2289.5,2768.5) ; 2283.71,2803.05 R128.2@2286,2826.5 ; v1@2285,2771 2287,2771 v1(2289.5,2768.5) ; v1@2285,2771 R130.2@2285,2793 ; v1@2285,2771 R130.2@2293.56,2791.29 ; v1@2285,2771 R130.2@2289.23,2792.61 ; v1@2285,2771 R130.2@2286,2793 ; R130.2@2285,2793 R130.2@2286,2793 ; R130.2@2285,2793 2285,2826.5 R128.2@2286,2826.5 ; R130.2@2285,2793 v1(2289.5,2768.5) ; R130.2@2285,2802.98 R128.2@2286,2826.5 ; R128.2@2285,2816.52 R130.2@2286,2793 ; R130.2@2285.62,2802.04 R128.2@2286,2826.5 ; R130.2@2286,2793 v1(2289.5,2768.5) ; R128.2@2286,2826.5 R130.2@2291.15,2800.81 ; R128.2@2286,2826.5 R130.2@2287.78,2801.3 ; R130.2@2289.23,2792.61 v1(2289.5,2768.5) ; v1(2289.5,2768.5) R130.2@2293.56,2791.29
ANT_TRNB: R129.2 R131.2 U1.E4 | length 2807.2
  Top w4.5: v2@2549.26,2359.11 U1.E4@2551.27,2343.28 ; v2@2549.72,2356.53 U1.E4@2558.54,2343.28 ; v2@2560.26,2356.47 U1.E4@2551.27,2343.28 ; v2@2560.75,2359.04 U1.E4@2558.54,2343.28 ; U1.E4@2551.27,2343.28 v2@2554.9,2358.7 ; U1.E4@2551.27,2343.28 v2(2555,2358.8) ; U1.E4@2554.9,2342.86 v2@2554.9,2358.7 ; U1.E4@2554.9,2342.86 v2@2554.9,2358.7 ; U1.E4@2554.9,2342.86 2560.65,2357.73 U1.E4@2554.9,2342.86 ; U1.E4@2554.9,2342.86 2549.34,2357.8 U1.E4@2554.9,2342.86 ; U1.E4@2554.9,2342.86 v2(2555,2358.8) ; U1.E4@2554.9,2342.86 v2(2555,2358.8) ; v2@2554.9,2358.7 v2(2555,2358.8) ; v2@2554.9,2358.7 U1.E4@2558.54,2343.28 ; v2(2555,2358.8) U1.E4@2558.54,2343.28
  Inner Layer 3 w4.5: v1@2302.34,2848.82 2310,2824.5 ; v1@2306.76,2849.79 2310,2824.5 ; v1@2313.24,2849.79 2310,2824.5 ; v1@2317.66,2848.82 2310,2824.5 ; v2@2554.16,2353.11 2535.23,2358.8 ; v2@2554.16,2364.49 2535.23,2358.8 ; v2(2555,2358.8) 2535.23,2358.8 ; 2310,2824.5 v1(2310,2850) 2310,2591 2516.05,2384.95 2516.05,2377.98 2535.23,2358.8
  Bottom w4.5: R129.2@2277.27,2891.99 R131.2@2282.66,2869.06 ; R129.2@2277.26,2892.95 R131.2@2279.74,2868.65 ; R131.2@2277.31,2860.45 R129.2@2284,2883.02 ; R129.2@2277.31,2891.55 R131.2@2284,2868.98 ; R129.2@2277.33,2891.37 R131.2@2284.62,2868.41 ; R129.2@2277.45,2890.74 R131.2@2286.8,2867.72 ; R129.2@2277.73,2889.82 R131.2@2290.18,2867.24 ; R131.2@2281.75,2859.59 R129.2@2284,2883.02 ; R129.2@2281.75,2892.33 R131.2@2284.62,2868.41 ; R129.2@2281.75,2892.41 R131.2@2284,2868.98 ; R129.2@2281.75,2892.6 R131.2@2282.66,2869.06 ; R129.2@2281.78,2892.05 R131.2@2286.8,2867.72 ; R129.2@2281.79,2892.99 R131.2@2279.74,2868.65 ; R129.2@2281.86,2891.65 R131.2@2290.18,2867.24 ; R131.2@2284.31,2856.32 v1@2305,2853.5 ; R129.2@2288.12,2891.59 R131.2@2279.74,2868.65 ; R129.2@2288.2,2891.95 R131.2@2282.66,2869.06 ; R129.2@2288.22,2892.95 R131.2@2290.18,2867.24 ; R131.2@2288.23,2859.86 R129.2@2284,2883.02 ; R129.2@2288.23,2892.14 R131.2@2284,2868.98 ; R129.2@2288.24,2892.23 R131.2@2284.62,2868.41 ; R129.2@2288.25,2892.52 R131.2@2286.8,2867.72 ; R129.2@2292.21,2889.65 R131.2@2279.74,2868.65 ; R129.2@2292.48,2890.47 R131.2@2282.66,2869.06 ; R131.2@2292.58,2861.1 R129.2@2284,2883.02 ; R129.2@2292.58,2890.9 R131.2@2284,2868.98 ; R129.2@2292.63,2891.13 R131.2@2284.62,2868.41 ; R129.2@2292.72,2891.85 R131.2@2286.8,2867.72 ; R129.2@2292.74,2892.9 R131.2@2290.18,2867.24 ; v1@2304.46,2844.58 R131.2@2288.57,2866.38 ; v1@2305.44,2843.73 R131.2@2286.17,2862.53 ; v1@2306.21,2843.24 R131.2@2285.29,2859.41 ; v1@2307.04,2842.84 R131.2@2284.67,2856.27 ; v1@2307.23,2842.76 R131.2@2290,2853.5 ; v1@2307.87,2847.54 R131.2@2288.57,2866.38 ; v1@2308.31,2842.44 R131.2@2284.19,2851.79 ; v1@2308.32,2847.22 R131.2@2286.17,2862.53 ; v1@2308.66,2847.04 R131.2@2285.29,2859.41 ; v1@2309.02,2846.9 R131.2@2284.67,2856.27 ; v1@2309.19,2846.85 R131.2@2290,2853.5 ; v1@2309.37,2857.72 R131.2@2284.19,2851.79 ; v1@2309.57,2846.78 R131.2@2284.19,2851.79 ; v1@2309.85,2857.75 R131.2@2290,2853.5 ; v1@2310.02,2853.25 R131.2@2284.19,2851.79 ; v1@2310.3,2853.24 R131.2@2290,2853.5 ; v1@2310.58,2853.2 R131.2@2284.67,2856.27 ; v1@2310.73,2857.72 R131.2@2284.67,2856.27 ; v1@2310.97,2853.1 R131.2@2285.29,2859.41 ; v1@2311.34,2852.96 R131.2@2286.17,2862.53 ; v1@2311.67,2857.57 R131.2@2285.29,2859.41 ; v1@2311.81,2852.7 R131.2@2288.57,2866.38 ; v1@2312.58,2857.31 R131.2@2286.17,2862.53 ; v1@2313.77,2856.77 R131.2@2288.57,2866.38 ; R131.2@2279.74,2868.65 R129.2@2285,2892.5 ; R131.2@2282.66,2869.06 R129.2@2285,2892.5 ; R131.2@2284,2859.5 R131.2@2290,2853.5 ; R131.2@2284,2859.5 R131.2@2285,2859.5 ; R131.2@2284,2859.5 2284,2892.5 R129.2@2285,2892.5 ; R131.2@2284,2868.98 R129.2@2285,2892.5 ; R129.2@2284,2883.02 R131.2@2285,2859.5 ; R131.2@2284.19,2851.79 v1@2305,2853.5 ; R131.2@2284.19,2851.79 v1(2310,2850) ; R131.2@2284.62,2868.41 R129.2@2285,2892.5 ; R131.2@2284.67,2856.27 v1(2310,2850) ; R131.2@2285,2859.5 v1@2305,2853.5 ; R129.2@2285,2892.5 R131.2@2290.18,2867.24 ; R129.2@2285,2892.5 R131.2@2286.8,2867.72 ; R131.2@2285.29,2859.41 v1(2310,2850) ; R131.2@2286.17,2862.53 v1@2305,2853.5 ; R131.2@2286.17,2862.53 v1(2310,2850) ; R131.2@2288.57,2866.38 v1@2305,2853.5 ; R131.2@2288.57,2866.38 v1(2310,2850) ; R131.2@2290,2853.5 v1@2305,2853.5 ; R131.2@2290,2853.5 v1(2310,2850) ; v1@2305,2853.5 v1(2310,2850)
APCK_RFCKO_N: J6.13 R382.2 | length 2319.8
  Top w5: R382.2@3253.9,2526.28 3270.88,2532.88 ; R382.2@3258,2520 3270.88,2532.88 ; R382.2@3264.28,2515.9 3270.88,2532.88 ; v1@3565.53,3354.68 3566.5,3324.1 ; v1@3580.08,3351.52 3566.5,3324.1 ; v1@3599.19,3856.05 J6.13@3624.45,3849.88 ; v1@3601.1,3855.55 J6.13@3628.47,3856.02 ; v1@3601.42,3870.48 3618,3868 ; v1@3602.96,3870.44 J6.13@3629.69,3863.2 ; v1@3603.07,3855.58 J6.13@3629.69,3863.2 ; v1@3604.89,3869.92 J6.13@3628.47,3856.02 ; v1@3605.78,3856.52 3618,3868 ; v1@3606.68,3868.86 J6.13@3624.45,3849.88 ; J6.13@3630.74,3863.01 v1@3603.47,3868 ; J6.13@3658,3856.02 3655.02,3859 3627,3859 3618,3868 ; 3270.88,2532.88 3277.5,2532.88 3566.5,2821.88 3566.5,3347.5 v1(3573,3354) 3566.5,3324.1 ; v1(3602,3863) 3601,3864 3601,3867 3602,3868 3618,3868 ; v1(3602,3863) 3618,3868 ; v1(3602,3863) J6.13@3624.45,3849.88 ; v1(3602,3863) J6.13@3629.69,3863.2 ; v1(3602,3863) J6.13@3628.47,3856.02 ; v1@3603.47,3868 J6.13@3624.45,3849.88 ; v1@3603.47,3868 J6.13@3628.47,3856.02 ; 3618,3868 3621.98,3852.6 3618,3868 ; 3618,3868 3632.74,3862 3618,3868 ; 3618,3868 J6.13@3628.47,3856.02 ; 3618,3868 J6.13@3628.47,3856.02
  Bottom w5: v1@3565.56,3353.05 3565.5,3383.21 ; v1@3579.98,3356.75 3565.5,3383.21 ; v1@3598.18,3856.55 3587.06,3867.5 ; v1@3602.37,3870.49 3587.06,3867.5 ; 3565.5,3383.21 v1(3573,3354) 3572,3355 3565.5,3355 3565.5,3845.94 3587.06,3867.5 ; 3587.06,3867.5 3599,3867.5 3602,3864.5 v1(3602,3863) 3587.06,3867.5
APCK_RFCKO_P: J6.11 R383.2 | length 2082.2
  Top w5: R383.2@3255.37,2547.98 3274,2545 ; R383.2@3263.16,2560.44 3274,2545 ; v1@3541.03,3350.23 3555.5,3323.94 ; v1@3555.44,3353.95 3555.5,3323.94 ; v1@3603.09,3882.75 J6.11@3626.57,3880.43 ; v1@3604.64,3897.49 J6.11@3628.1,3894.85 ; v1@3605.41,3882.51 J6.11@3628.47,3887.52 ; v1@3606.04,3882.57 3632,3890 v1@3606.04,3897.43 ; v1@3606.96,3897.24 J6.11@3628.47,3887.52 ; v1@3607.69,3883 J6.11@3628.1,3894.85 ; v1@3609.09,3896.28 J6.11@3626.57,3880.43 ; J6.11@3658,3887.52 3658,3890 v1(3605,3890) ; 3274,2545 3555.5,2826.5 3555.5,3353 v1(3548,3353) 3555.5,3323.94 ; 3274,2545 3267,2545 3257,2555 R383.2@3258,2555 3274,2545 ; v1(3605,3890) J6.11@3626.57,3880.43 ; v1(3605,3890) J6.11@3628.1,3894.85 ; v1(3605,3890) J6.11@3628.47,3887.52
  Bottom w5: v1@3540.96,3355.59 3554.5,3381.57 ; v1@3555.47,3352.29 3554.5,3381.57 ; v1(3605,3890) 3605,3889 3594.5,3878.5 3582.5,3878.5 3554.5,3850.5 3554.5,3353 v1(3548,3353) 3554.5,3381.57
APCK_RFCKON_1-CPU-RT0: R382.1 U1.B11 | length 773.2
  Top w5: U1.B11@2735.86,2270.48 2758.64,2270.48 ; U1.B11@2736.11,2267.08 2758.64,2270.48 ; U1.B11@2736.11,2273.87 2758.64,2270.48 ; R382.1@3218.39,2513.43 3203.75,2525.75 ; R382.1@3222.81,2527.46 3203.75,2525.75 ; R382.1@3223,2520 R382.1@3222,2520 ; 2758.64,2270.48 2765.74,2277.57 2766.06,2277.57 2797.54,2309.05 2980.94,2309.05 3197.64,2525.75 3203.75,2525.75 ; 3203.75,2525.75 3209.5,2520 ; 3203.75,2525.75 R382.1@3222,2520 ; 3209.5,2520 R382.1@3222,2520 ; 3209.5,2520 3219.75,2512.85 3209.5,2520 ; 3209.5,2520 3219.75,2527.15 3209.5,2520 ; 3209.5,2520 R382.1@3222,2520 ; 3209.5,2520 R382.1@3222,2520
APCK_RFCKOP_1-CPU-RT0: R383.1 U1.A11 | length 700.5
  Top w5: U1.A11@2752.38,2291.59 2773.67,2300.74 ; U1.A11@2755.95,2285.81 2773.67,2300.74 ; R383.1@3215.98,2559.48 3203.75,2536.75 ; R383.1@3223,2555 R383.1@3222,2555 3203.75,2536.75 ; R383.1@3226.48,2548.98 3203.75,2536.75 ; 2773.67,2300.74 U1.A11@2753.95,2288.57 2761.5,2288.57 2792.98,2320.05 2976.39,2320.05 3193.08,2536.75 3203.75,2536.75
BBPLL_V12A_1-CPU-RT0: C36.1 R23.2 U1.A7 | length 317.1
  Top w8: U1.A7@2680.6,2361.92 U1.A7@2681.57,2360.95 ; U1.A7@2680.6,2361.92 v2@2693.34,2374.66 ; U1.A7@2680.6,2361.92 v2(2692,2376) ; U1.A7@2681.57,2360.95 v2@2693.34,2374.66 ; U1.A7@2681.57,2360.95 v2(2692,2376) ; v2(2692,2376) v2@2693.34,2374.66
  Bottom w12: C36.1@2700.27,2441.27 2704.56,2441.27 2716,2429.83 2716,2421 2690,2395 ; 2690,2395 2690,2376 v2(2692,2376) 2690,2395
  Bottom w20: C36.1@2700.27,2441.27 R23.2@2676.02,2417.02 C36.1@2700.27,2441.27 ; C36.1@2700.27,2441.27 2676.73,2417.73 C36.1@2700.27,2441.27
BG_RES_12K_1-CPU-RT0: C83.1 R107.1 U1.A4 | length 568.3
  Top w4.5: U1.A4@2624.98,2418.07 2640.05,2428 ; U1.A4@2627.29,2415.24 2640.05,2428 ; U1.A4@2630.12,2412.93 2640.05,2428 ; C83.1@2835.53,2566.09 2832,2552 ; C83.1@2839.73,2564.3 2832,2552 ; C83.1@2844.3,2559.73 2832,2552 ; C83.1@2846.09,2555.53 2832,2552 ; 2640.05,2428 2662,2428 2786,2552 2832,2552 ; 2832,2552 C83.1@2842.27,2562.27 2832,2552
  Top w5: C83.1@2834.85,2563.37 2842.27,2588 ; C83.1@2842.27,2562.27 2842.27,2588 ; C83.1@2849.69,2563.37 2842.27,2588 ; R107.1@2895.59,2618.84 2893.43,2631.15 ; R107.1@2902.25,2622.29 2893.43,2631.15 ; R107.1@2905.73,2628.94 2893.43,2631.15 ; 2842.27,2588 2885.42,2631.15 2893.43,2631.15
BS1_5-POWER0: C309.1 U616.1 | length 908.4
  Top w4.5: C309.1@7005.29,2451.26 U616.1@7011.42,2427.82 ; C309.1@7005.37,2450.61 U616.1@7013.33,2428.5 ; C309.1@7005.43,2450.35 U616.1@7014.15,2428.49 ; C309.1@7005.58,2449.76 U616.1@7016.19,2427.97 ; C309.1@7005.79,2449.16 U616.1@7018.46,2427.56 ; C309.1@7006.19,2448.3 U616.1@7021.89,2427.49 ; C309.1@7009.77,2451.62 U616.1@7014.15,2428.49 ; C309.1@7009.76,2451.73 U616.1@7013.33,2428.5 ; C309.1@7009.75,2451.99 U616.1@7011.42,2427.82 ; C309.1@7009.81,2451.36 U616.1@7016.19,2427.97 ; C309.1@7009.88,2451.09 U616.1@7018.46,2427.56 ; C309.1@7010.02,2450.7 U616.1@7021.89,2427.49 ; U616.1@7010.21,2418.56 C309.1@7013.33,2442.44 ; U616.1@7014.74,2418.4 C309.1@7013.33,2442.44 ; C309.1@7016.12,2452.92 U616.1@7021.89,2427.49 ; C309.1@7016.22,2451.57 U616.1@7011.42,2427.82 ; C309.1@7016.21,2452.5 U616.1@7018.46,2427.56 ; C309.1@7016.25,2451.82 U616.1@7013.33,2428.5 ; C309.1@7016.25,2451.93 U616.1@7014.15,2428.49 ; C309.1@7016.24,2452.21 U616.1@7016.19,2427.97 ; U616.1@7018,2399.33 7013.33,2404 7013.33,2451.67 C309.1@7013,2452 ; U616.1@7018,2418.82 C309.1@7013.33,2442.44 ; C309.1@7020.55,2450.27 U616.1@7011.42,2427.82 ; C309.1@7020.6,2453.53 U616.1@7021.89,2427.49 ; C309.1@7020.66,2450.83 U616.1@7013.33,2428.5 ; C309.1@7020.7,2451.1 U616.1@7014.15,2428.49 ; C309.1@7020.75,2451.78 U616.1@7016.19,2427.97 ; C309.1@7020.73,2452.5 U616.1@7018.46,2427.56 ; U616.1@7021.18,2419.68 C309.1@7013.33,2442.44 ; U616.1@7025.3,2421.55 C309.1@7013.33,2442.44 ; U616.1@7011.42,2427.82 C309.1@7013,2452 ; C309.1@7013,2452 U616.1@7013.33,2428.5 ; C309.1@7013,2452 U616.1@7014.15,2428.49 ; C309.1@7013,2452 U616.1@7016.19,2427.97 ; C309.1@7013,2452 U616.1@7021.89,2427.49 ; C309.1@7013,2452 U616.1@7018.46,2427.56
BS_1_5-POWER0: C14.1 R8.1 | length 951.4
  Top w4.5: C14.1@6995.25,1847.25 6998.36,1823.02 ; C14.1@6995.28,1846.33 7001.17,1823.39 ; R8.1@6995.36,1814.28 7003,1836.5 ; C14.1@6995.36,1845.72 7003,1823.5 ; C14.1@6995.46,1845.19 R8.1@7005.01,1822.06 ; C14.1@6995.72,1844.35 R8.1@7008.17,1821.48 ; R8.1@6999.76,1813.22 7003,1836.5 ; C14.1@6999.76,1846.78 7003,1823.5 ; C14.1@6999.75,1847.03 7001.17,1823.39 ; C14.1@6999.77,1847.4 6998.36,1823.02 ; C14.1@6999.78,1846.53 R8.1@7005.01,1822.06 ; C14.1@6999.86,1846.16 R8.1@7008.17,1821.48 ; R8.1@7003,1813 C14.1@7003,1847 ; C14.1@7006.14,1846.17 6998.36,1823.02 ; C14.1@7006.22,1846.53 7001.17,1823.39 ; C14.1@7006.22,1847.45 R8.1@7008.17,1821.48 ; R8.1@7006.24,1813.22 7003,1836.5 ; C14.1@7006.24,1846.78 7003,1823.5 ; C14.1@7006.25,1847.05 R8.1@7005.01,1822.06 ; C14.1@7010.28,1844.34 6998.36,1823.02 ; C14.1@7010.53,1845.15 7001.17,1823.39 ; R8.1@7010.64,1814.28 7003,1836.5 ; C14.1@7010.64,1845.72 7003,1823.5 ; C14.1@7010.73,1846.42 R8.1@7005.01,1822.06 ; C14.1@7010.74,1847.39 R8.1@7008.17,1821.48 ; C14.1@6995.8,1844.14 7003,1836.5 ; C14.1@6995.8,1844.14 7003,1836.5 ; C14.1@6995.8,1844.14 7003,1836.5 ; C14.1@6995.8,1844.14 7003,1836.5 ; 6998.36,1823.02 C14.1@7003,1847 ; C14.1@6999.79,1846.5 7003,1836.5 ; C14.1@6999.79,1846.5 7003,1836.5 ; C14.1@6999.79,1846.5 7003,1836.5 ; C14.1@6999.79,1846.5 7003,1836.5 ; 7001.17,1823.39 C14.1@7003,1847 ; 7003,1823.5 C14.1@7003,1847 ; 7003,1836.5 C14.1@7010.2,1844.14 ; 7003,1836.5 C14.1@7006.21,1846.5 ; 7003,1836.5 C14.1@7003,1847 ; 7003,1836.5 C14.1@7010.2,1844.14 ; 7003,1836.5 C14.1@7006.21,1846.5 ; 7003,1836.5 C14.1@7003,1847 ; 7003,1836.5 C14.1@7010.2,1844.14 ; 7003,1836.5 C14.1@7006.21,1846.5 ; 7003,1836.5 C14.1@7003,1847 ; 7003,1836.5 C14.1@7010.2,1844.14 ; 7003,1836.5 C14.1@7006.21,1846.5 ; 7003,1836.5 C14.1@7003,1847 ; C14.1@7003,1847 R8.1@7008.17,1821.48 ; C14.1@7003,1847 R8.1@7005.01,1822.06
BS_2_5-POWER0: C3.1 R2.1 | length 935.2
  Top w4.5: R2.1@6796,3025 C3.1@6830,3025 ; R2.1@6796.22,3021.76 6819.5,3025 ; R2.1@6796.22,3028.24 6819.5,3025 ; R2.1@6797.28,3017.36 6819.5,3025 ; R2.1@6797.28,3032.64 6819.5,3025 ; C3.1@6827.34,3017.72 6806.23,3029.56 ; C3.1@6827.34,3032.28 6806.02,3020.36 ; C3.1@6828.14,3017.48 6806.44,3026.82 ; C3.1@6828.15,3032.53 6806.39,3023.17 ; C3.1@6828.72,3017.36 6806.5,3025 ; C3.1@6828.72,3032.64 6806.5,3025 ; C3.1@6829.17,3021.86 6806.23,3029.56 ; C3.1@6829.17,3028.14 6806.02,3020.36 ; C3.1@6829.32,3032.72 6806.44,3026.82 ; C3.1@6829.33,3017.28 6806.39,3023.17 ; C3.1@6829.53,3021.78 6806.44,3026.82 ; C3.1@6829.53,3028.22 6806.39,3023.17 ; C3.1@6829.78,3021.76 6806.5,3025 ; C3.1@6829.78,3028.24 6806.5,3025 ; C3.1@6830.03,3021.75 6806.39,3023.17 ; C3.1@6830.03,3028.25 6806.44,3026.82 ; C3.1@6830.22,3032.75 6806.23,3029.56 ; C3.1@6830.24,3017.25 6806.02,3020.36 ; C3.1@6830.4,3021.77 6806.02,3020.36 ; C3.1@6830.4,3028.23 6806.23,3029.56 ; 6806.02,3020.36 C3.1@6830,3025 ; 6806.23,3029.56 C3.1@6830,3025 ; 6806.39,3023.17 C3.1@6830,3025 ; 6806.44,3026.82 C3.1@6830,3025 ; 6806.5,3025 C3.1@6830,3025 ; 6819.5,3025 C3.1@6827.14,3017.8 ; 6819.5,3025 C3.1@6827.14,3032.2 ; 6819.5,3025 C3.1@6829.5,3021.79 ; 6819.5,3025 C3.1@6829.5,3028.21 ; 6819.5,3025 C3.1@6830,3025 ; 6819.5,3025 C3.1@6827.14,3017.8 ; 6819.5,3025 C3.1@6827.14,3032.2 ; 6819.5,3025 C3.1@6829.5,3021.79 ; 6819.5,3025 C3.1@6829.5,3028.21 ; 6819.5,3025 C3.1@6830,3025 ; 6819.5,3025 C3.1@6827.14,3017.8 ; 6819.5,3025 C3.1@6827.14,3032.2 ; 6819.5,3025 C3.1@6829.5,3021.79 ; 6819.5,3025 C3.1@6829.5,3028.21 ; 6819.5,3025 C3.1@6830,3025 ; 6819.5,3025 C3.1@6827.14,3017.8 ; 6819.5,3025 C3.1@6827.14,3032.2 ; 6819.5,3025 C3.1@6829.5,3021.79 ; 6819.5,3025 C3.1@6829.5,3028.21 ; 6819.5,3025 C3.1@6830,3025
BS_11_5-POWER0: D38.2 R8.2 U3.1 | length 668.5
  Top w4.5: U3.1@6929.88,1781.16 6964.38,1775 ; U3.1@6930.96,1785.55 6964.38,1775 ; U3.1@6935.8,1795.29 6964.38,1775 ; U3.1@6938.65,1798.8 6964.38,1775 ; R8.2@7001.09,1784.51 6979.4,1775 ; R8.2@7002.38,1769.27 6979.4,1775 ; R8.2@7002.5,1780.21 6979.4,1775 ; R8.2@7002.81,1780.24 7026.79,1780 ; R8.2@7003.05,1773.75 6979.4,1775 ; R8.2@7003.29,1784.74 7026.79,1780 ; R8.2@7003.62,1773.81 7026.79,1780 ; R8.2@7005.2,1769.57 7026.79,1780 ; D38.2@7038.72,1772.36 7016.5,1780 ; D38.2@7038.72,1787.64 7016.5,1780 ; D38.2@7039.78,1776.76 7016.5,1780 ; D38.2@7039.78,1783.24 7016.5,1780 ; 6964.38,1775 U3.1@6933,1790.61 6933,1775 7008,1775 7008,1778 R8.2@7003,1778 ; 6979.4,1775 R8.2@7003,1777 ; R8.2@7003,1777 R8.2@7003,1778 ; R8.2@7003,1777 7026.79,1780 ; R8.2@7003,1778 7005,1780 D38.2@7040,1780 7016.5,1780
BS_21_5-POWER0: D39.2 R2.2 U2.1 | length 1211.7
  Top w4.5: U2.1@6717.61,3081 6719.5,3081 6724.5,3076 6737,3076 6753,3060 6753,3025 R2.2@6760,3025 ; U2.1@6724.42,3072.57 6751.71,3061.29 ; U2.1@6726.47,3076.62 6751.71,3061.29 ; U2.1@6729.72,3081 6751.71,3061.29 ; U2.1@6733.72,3084.71 6751.71,3061.29 ; U2.1@6737.51,3087.19 6751.71,3061.29 ; R2.2@6752.31,3024.04 6753,3049.68 ; R2.2@6752.57,3022.8 D39.2@6763,3001.24 ; D39.2@6755.25,2992.9 R2.2@6758.83,3016.83 ; D39.2@6755.28,2993.64 R2.2@6761.06,3016.61 ; D39.2@6755.34,2991.83 R2.2@6755.41,3016.92 ; D39.2@6755.36,2994.28 R2.2@6763,3016.5 ; D39.2@6755.36,2994.33 R2.2@6763.16,3016.5 ; D39.2@6755.58,2995.24 R2.2@6766.13,3016.74 ; R2.2@6756.82,3024.31 6753,3049.68 ; R2.2@6756.81,3024.38 D39.2@6763,3001.24 ; D39.2@6759.77,2992.66 R2.2@6758.83,3016.83 ; D39.2@6759.75,2992.96 R2.2@6761.06,3016.61 ; D39.2@6759.76,2993.22 R2.2@6763,3016.5 ; D39.2@6759.76,2993.25 R2.2@6763.16,3016.5 ; D39.2@6759.81,2993.64 R2.2@6766.13,3016.74 ; D39.2@6759.84,2992.22 R2.2@6755.41,3016.92 ; R2.2@6763.06,3026.08 6753,3049.68 ; R2.2@6763.24,3025.19 D39.2@6763,3001.24 ; D39.2@6766.03,2994.18 R2.2@6755.41,3016.92 ; D39.2@6766.16,2993.77 R2.2@6758.83,3016.83 ; D39.2@6766.21,2993.49 R2.2@6761.06,3016.61 ; D39.2@6766.24,2992.79 R2.2@6766.13,3016.74 ; R2.2@6767.05,3028.22 6753,3049.68 ; R2.2@6767.74,3024.71 D39.2@6763,3001.24 ; D39.2@6769.94,2996.46 R2.2@6755.41,3016.92 ; D39.2@6770.32,2995.54 R2.2@6758.83,3016.83 ; D39.2@6770.52,2994.89 R2.2@6761.06,3016.61 ; D39.2@6770.65,2994.23 R2.2@6763.16,3016.5 ; D39.2@6770.64,2994.28 R2.2@6763,3016.5 ; D39.2@6770.75,2993.24 R2.2@6766.13,3016.74 ; 6753,3049.68 R2.2@6760,3025 ; R2.2@6755.41,3016.92 D39.2@6763,2993 ; R2.2@6758.83,3016.83 D39.2@6763,2993 ; R2.2@6760,3025 6761,3025 6763,3023 D39.2@6763,2993 ; R2.2@6760,3025 D39.2@6763,3001.24 ; R2.2@6761.06,3016.61 D39.2@6763,2993 ; D39.2@6763,2993 R2.2@6766.13,3016.74 ; D39.2@6763,2993 R2.2@6763.16,3016.5 ; R2.2@6763,3016.5 6766.24,2993.22 R2.2@6763.16,3016.5
CAP1_4-ETHERNET: C111.1 U12.3 | length 675.2
  Top w20: U12.3@2836,1210 C111.1@2836,1280 2836,1192 U12.3@2838,1190 ; C111.1@2836,1275.63 2822.45,1191.06 C111.1@2836,1275.77 ; C111.1@2836,1275.63 2853.49,1191.78 C111.1@2836,1275.77 ; C111.1@2836,1275.63 U12.3@2838,1190 ; C111.1@2836,1275.77 U12.3@2838,1190
CAP2_4-ETHERNET: C114.1 U14.3 | length 252
  Top w20: U14.3@1782.48,1191.45 C114.1@1798,1274 ; U14.3@1798,1190 C114.1@1798,1274 ; U14.3@1813.52,1191.45 C114.1@1798,1274
CAP3_4-ETHERNET: C121.1 U16.4 | length 543.4
  Top w18: U16.4@3623.5,1195.73 3640,1273.59 U16.4@3656.5,1195.73 ; U16.4@3623.52,1195.93 C121.1@3640.98,1273.59 ; U16.4@3640,1210.96 C121.1@3641,1275 3640,1274 U16.4@3640,1194 C121.1@3640.98,1273.59 ; U16.4@3656.52,1195.53 C121.1@3640.98,1273.59
CAP4_4-ETHERNET: C115.1 U14.8 | length 584
  Top w20: U14.8@1298,1206 C115.1@1298,1276 U14.8@1298,1190 C115.1@1298,1275.59 ; C115.1@1298,1275.59 1282.47,1191.42 C115.1@1298,1275.59 ; C115.1@1298,1275.59 1313.53,1191.42 C115.1@1298,1275.59
CAP5_4-ETHERNET: C112.1 U12.8 | length 631
  Top w20: U12.8@2340,1200 C112.1@2340,1270 ; U12.8@2338,1190 2340,1192 C112.1@2340,1270 ; U12.8@2338,1190 C112.1@2340,1270 ; U12.8@2338,1190 C112.1@2340,1270 ; C112.1@2340,1270 2322.53,1191.91 C112.1@2340,1270 ; C112.1@2340,1270 2353.55,1191.13 C112.1@2340,1270
CHANNEL_A+: C706.1 R783.2 T600.12 U607.18 | length 1139.3
  Top w5: U607.18@4604.22,1706.1 4618.04,1706.1 4622.94,1711 ; U607.18@4615.05,1706.1 4622.94,1711 ; T600.12@5068.84,1303.81 5092.05,1319.01 ; T600.12@5073.05,1264.54 5073.05,1300.01 5092.05,1319.01 ; T600.12@5073.05,1298.79 5092.05,1319.01 ; R783.2@5074.14,1344.43 5092.05,1338.01 ; R783.2@5074.91,1329.74 5092.05,1338.01 ; C706.1@5075.15,1434.41 5092.05,1428 ; C706.1@5075.96,1419.76 5092.05,1428 ; T600.12@5078.32,1294.9 5092.05,1319.01 ; 4622.94,1711 5010.46,1711 5092.05,1629.41 5092.05,1428 ; 5092.05,1319.01 5092.05,1338.01 ; 5092.05,1338.01 5073.05,1338.01 R783.2@5073.05,1337.01 5092.05,1338.01 ; 5092.05,1338.01 5092.05,1428 ; 5092.05,1428 5074,1428 C706.1@5074,1427 5092.05,1428
CHANNEL_A+_2: C718.1 R791.2 T601.12 U609.18 | length 1668.7
  Top w5: T601.12@5843.84,1308.81 5867.05,1324.01 ; T601.12@5848.05,1269.54 5848.05,1305.01 5867.05,1324.01 ; T601.12@5848.05,1303.79 5867.05,1324.01 ; C718.1@5848.03,1433.43 5867.05,1427 ; C718.1@5848.77,1418.71 5867.05,1427 ; R791.2@5849.14,1349.43 5867.05,1343.01 ; R791.2@5849.91,1334.74 5867.05,1343.01 ; T601.12@5853.32,1299.9 5867.05,1324.01 ; U609.18@5878.22,2124.1 5892.04,2124.1 5895.94,2128 ; 5909.4,2128 U609.18@5889.05,2124.1 ; 5867.05,1324.01 5867.05,1343.01 ; 5867.05,1343.01 5867.05,1427 ; 5867.05,1343.01 5848.05,1343.01 R791.2@5848.05,1342.01 5867.05,1343.01 ; 5867.05,1427 5847,1427 C718.1@5847,1426 5867.05,1427 ; 5867.05,1427 5867.05,1496.33 5867.05,1501.06 5927.99,1562 5938.55,1562 6017.2,1562 6227,1771.8 6227,2080.94 6179.94,2128 5895.94,2128 ; U609.18@5889.05,2124.1 5895.94,2128 ; U609.18@5889.05,2124.1 5895.94,2128
CHANNEL_A-: C707.1 R784.2 T600.11 U607.19 | length 1201.4
  Top w5: U607.19@4604.22,1725.78 4618.26,1725.78 4622.04,1722 ; 4635.38,1722 U607.19@4615.05,1725.78 ; T600.11@5117.8,1294.86 5103.05,1320.01 ; C707.1@5120.92,1419.81 5103.05,1429 ; R784.2@5121.28,1329.72 5103.05,1338.01 ; R784.2@5122.02,1344.44 5103.05,1338.01 ; C707.1@5122.39,1434.47 5103.05,1429 ; T600.11@5123.05,1264.54 5123.05,1300.01 5103.05,1320.01 ; T600.11@5123.05,1298.79 5103.05,1320.01 ; T600.11@5127.28,1303.79 5103.05,1320.01 ; U607.19@4615.05,1725.78 4622.04,1722 ; U607.19@4615.05,1725.78 4622.04,1722 ; 4622.04,1722 5015.02,1722 5103.05,1633.97 5103.05,1429 ; 5103.05,1320.01 5103.05,1338.01 ; 5103.05,1338.01 5123.05,1338.01 R784.2@5123.05,1337.01 5103.05,1338.01 ; 5103.05,1338.01 5103.05,1429 ; 5103.05,1429 5122.05,1429 5123.05,1428 C707.1@5123.05,1427 5103.05,1429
